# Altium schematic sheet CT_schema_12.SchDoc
size 632 x 434 mm
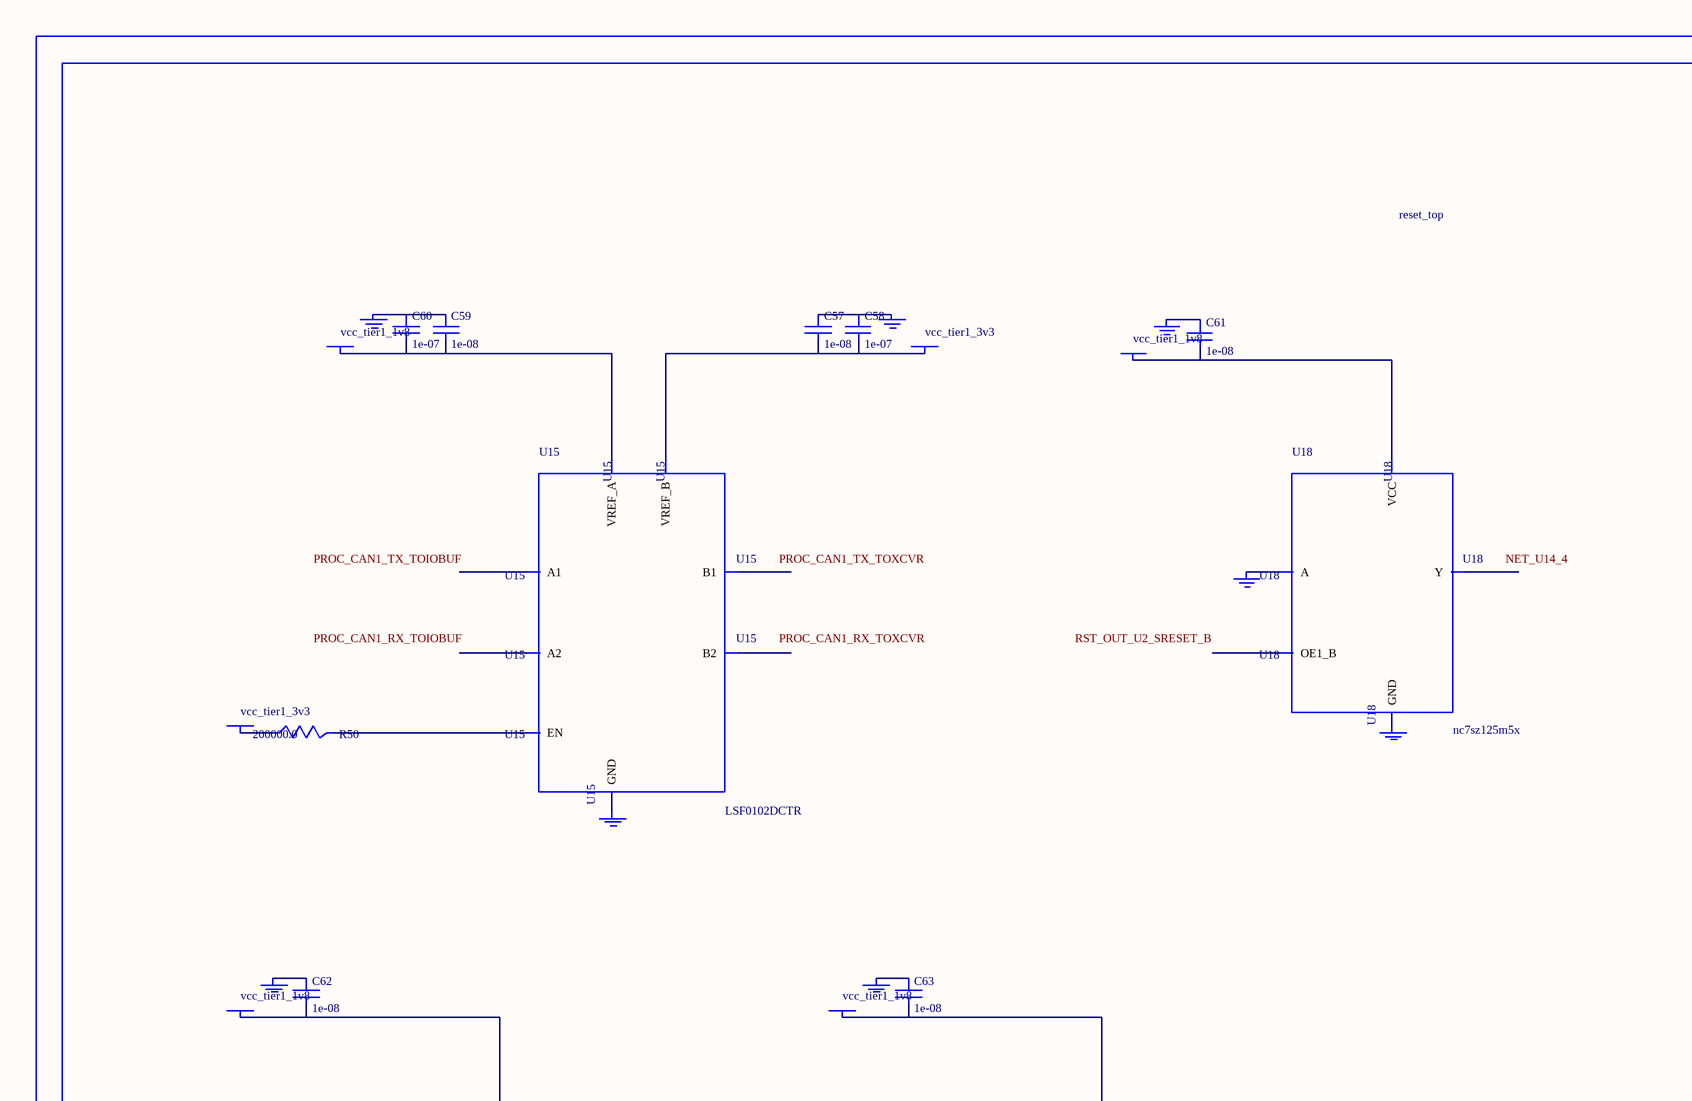
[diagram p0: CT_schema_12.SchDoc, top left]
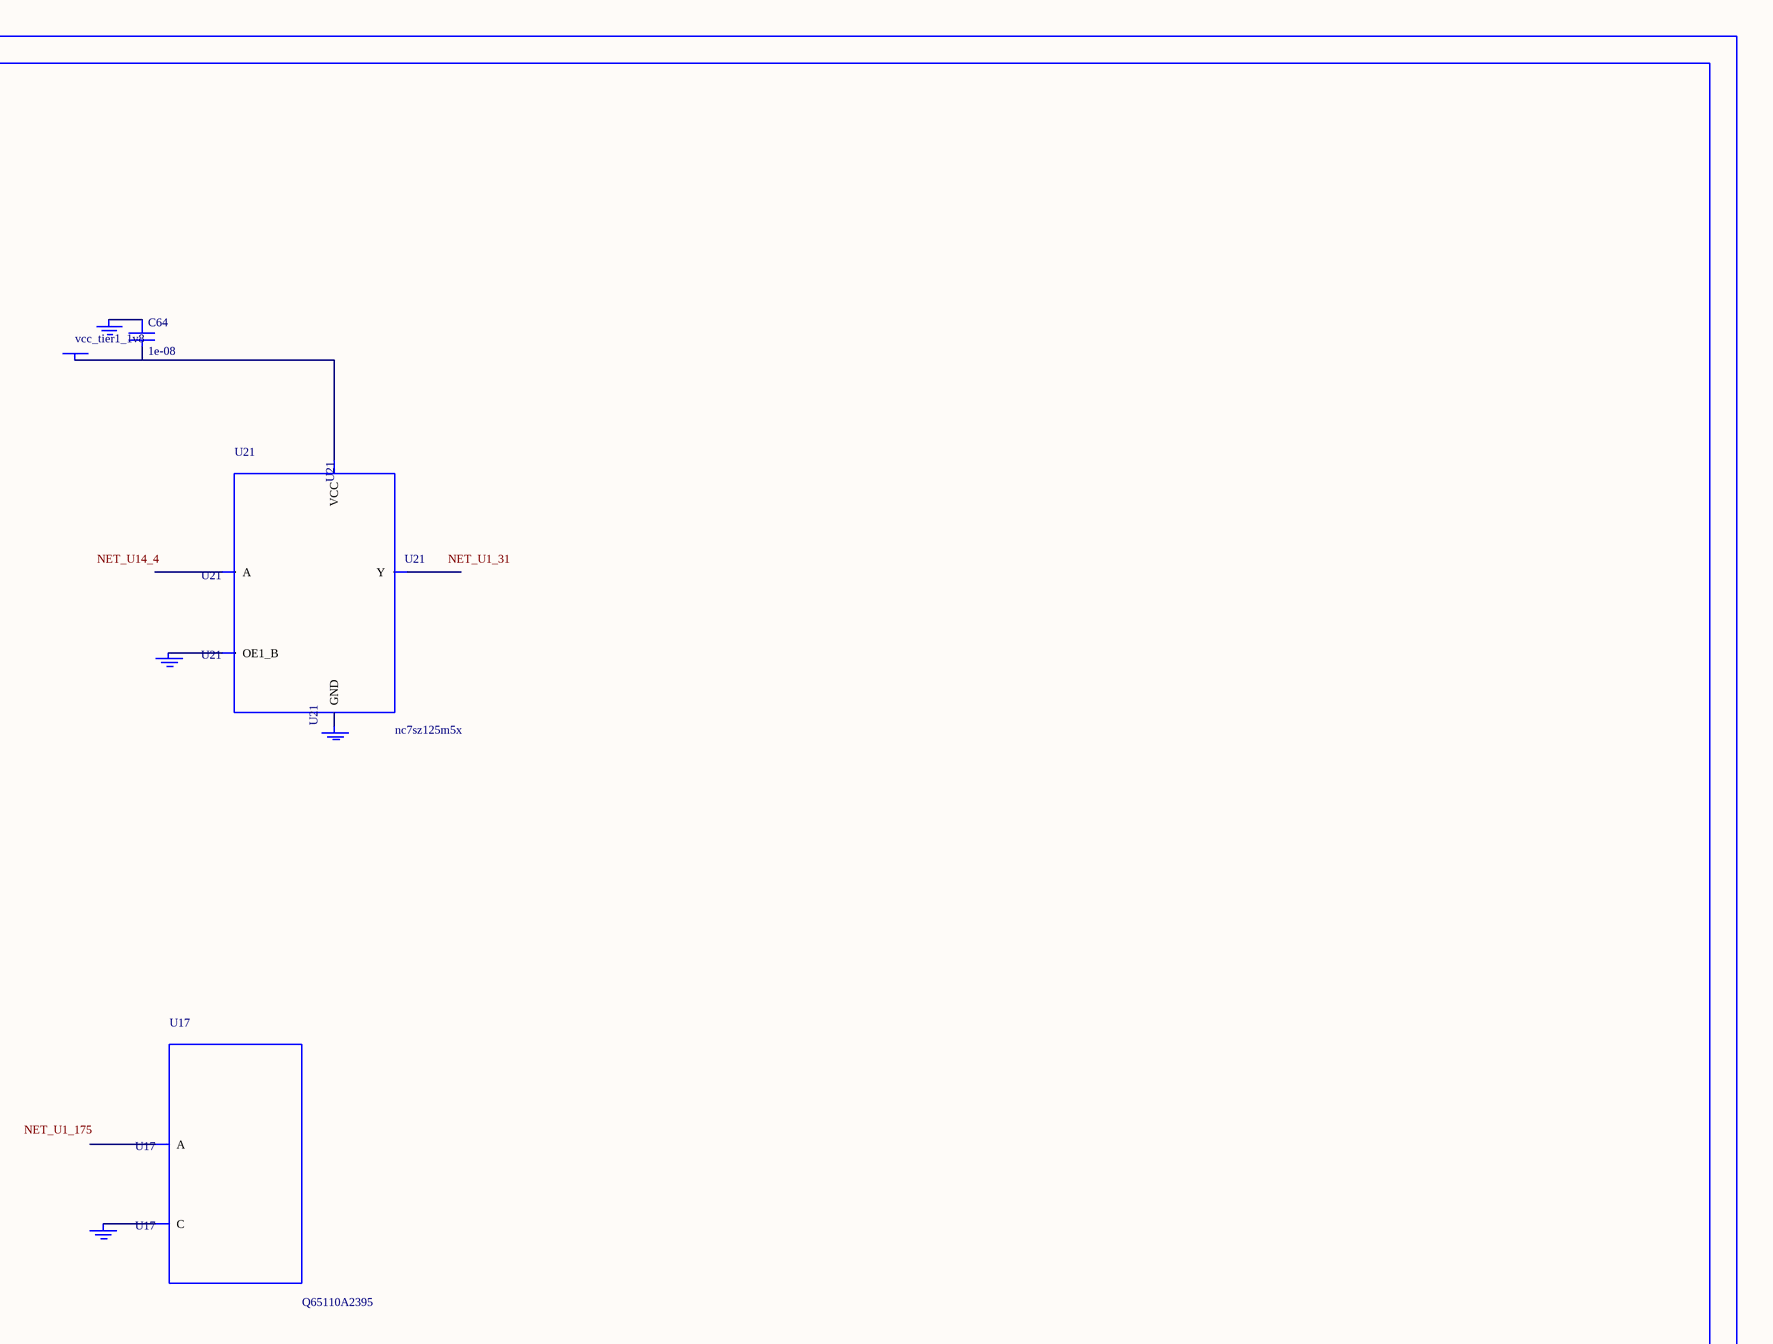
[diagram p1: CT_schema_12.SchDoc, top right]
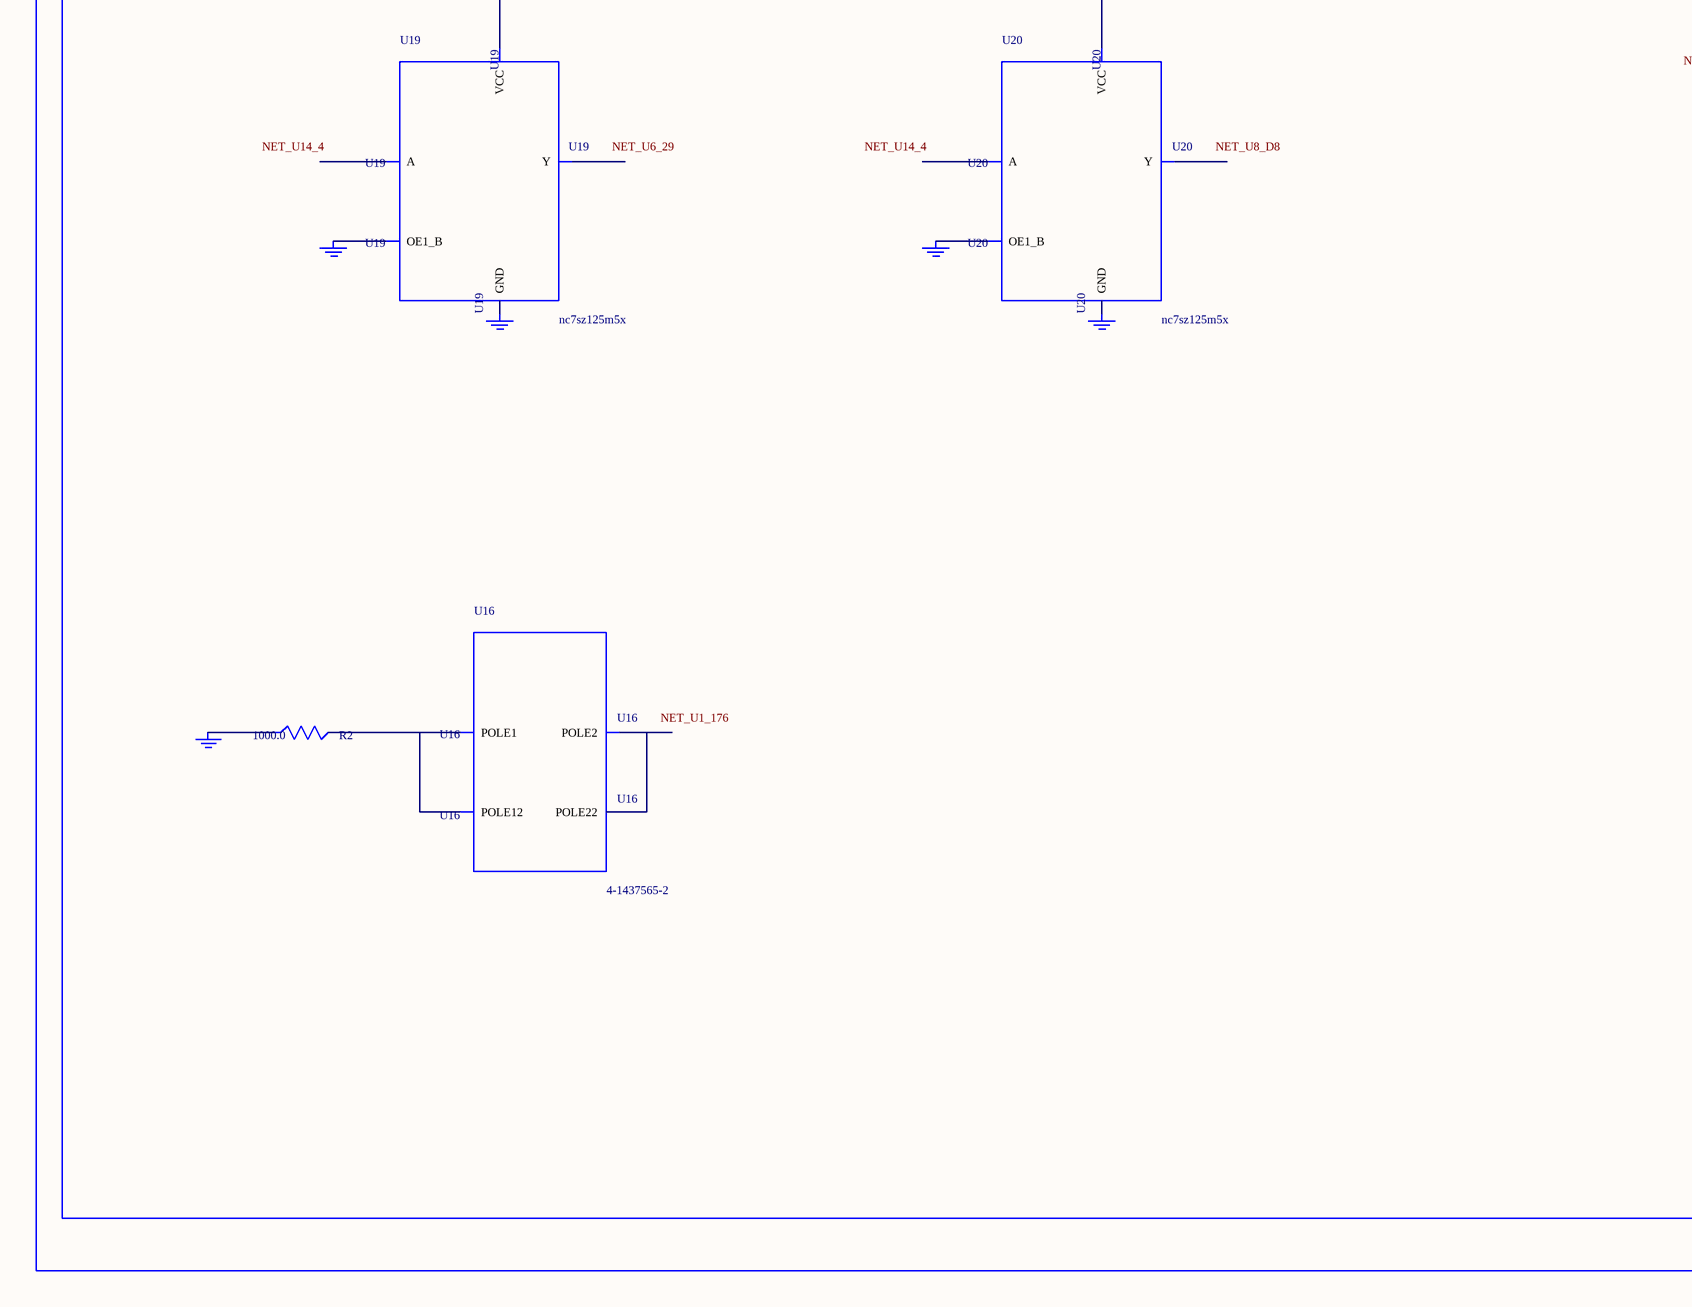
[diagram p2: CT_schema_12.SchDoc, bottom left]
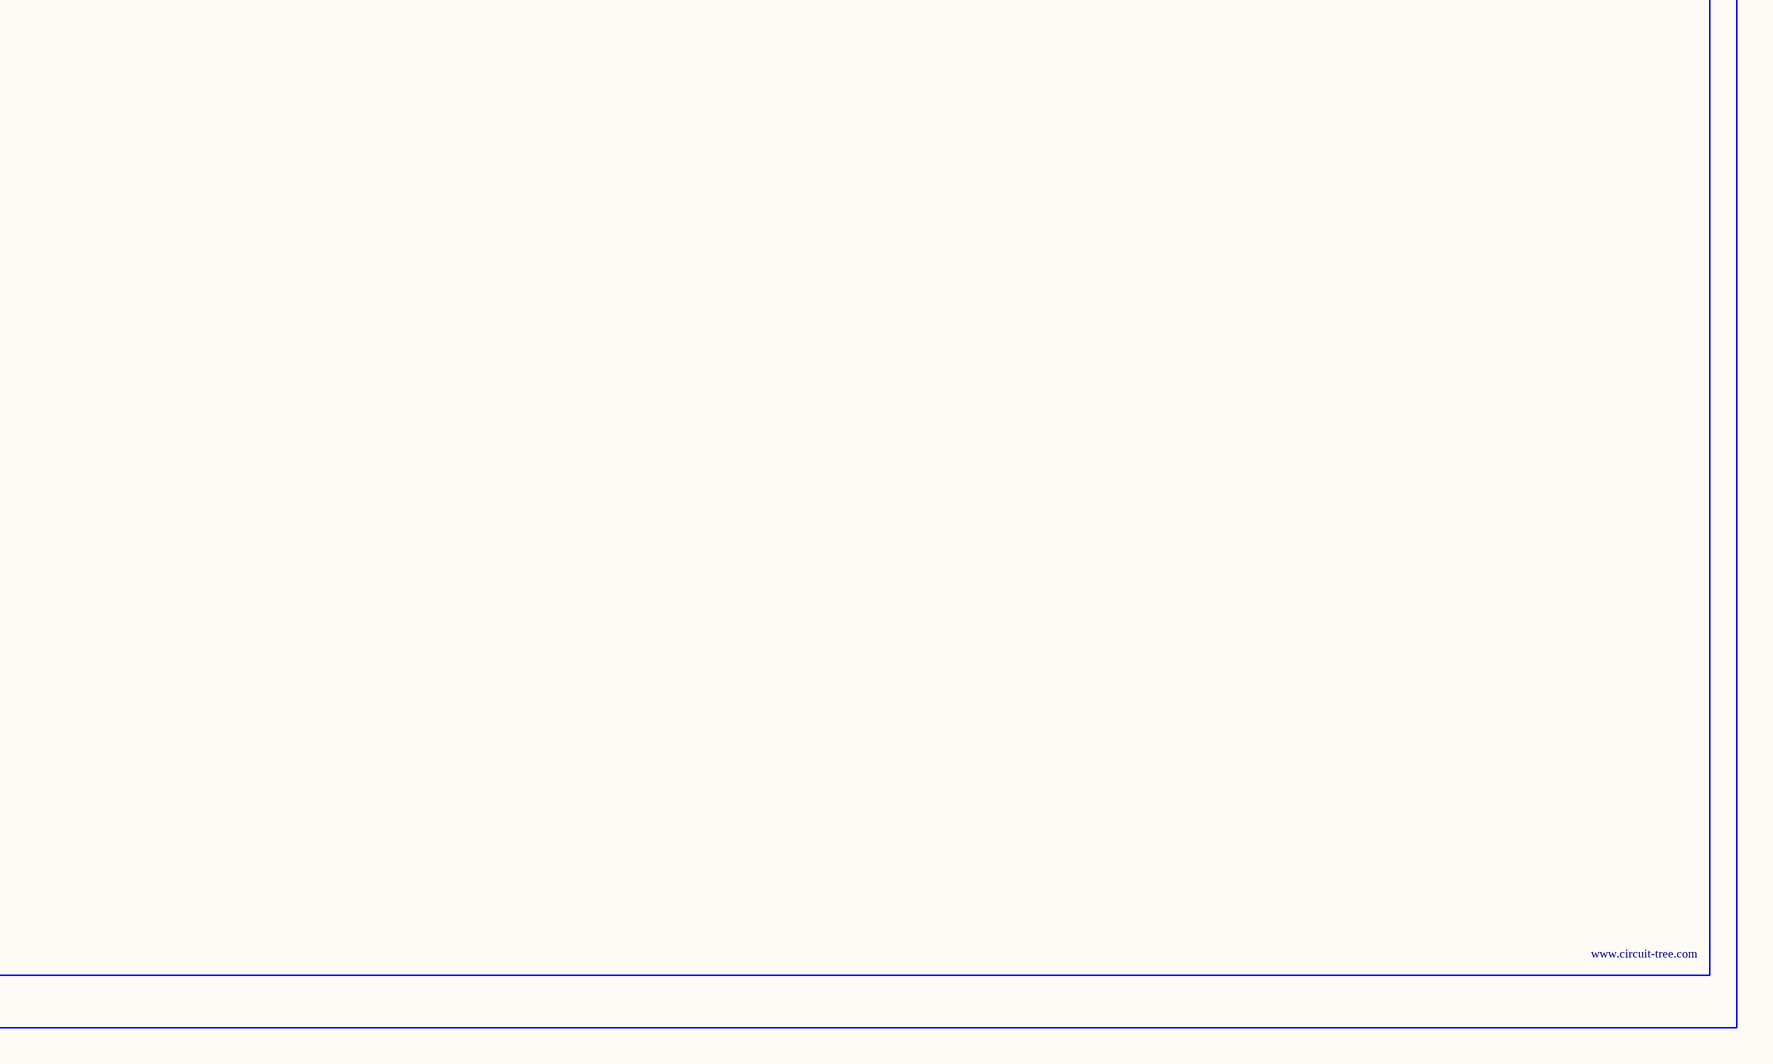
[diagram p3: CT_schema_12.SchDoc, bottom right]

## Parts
BORDER11  (no value)
C57  1e-08  [C0402]
C58  1e-07  [C0402]
C59  1e-08  [C0402]
C60  1e-07  [C0402]
C61  1e-08  [C0402]
C62  1e-08  [C0402]
C63  1e-08  [C0402]
C64  1e-08  [C0402]
GND_INSTANCE_11_0  (no value)
GND_INSTANCE_11_1  (no value)
GND_INSTANCE_11_2  (no value)
GND_INSTANCE_11_3  (no value)
GND_INSTANCE_11_4  (no value)
GND_INSTANCE_11_5  (no value)
GND_INSTANCE_11_6  (no value)
GND_INSTANCE_11_7  (no value)
GND_INSTANCE_11_8  (no value)
GND_INSTANCE_11_9  (no value)
GND_INSTANCE_11_10  (no value)
GND_INSTANCE_11_11  (no value)
GND_INSTANCE_11_12  (no value)
GND_INSTANCE_11_13  (no value)
GND_INSTANCE_11_14  (no value)
GND_INSTANCE_11_15  (no value)
GND_INSTANCE_11_16  (no value)
POWER_INSTANCE_11_0  vcc_tier1_1v8
POWER_INSTANCE_11_1  vcc_tier1_3v3
POWER_INSTANCE_11_2  vcc_tier1_3v3
POWER_INSTANCE_11_3  vcc_tier1_1v8
POWER_INSTANCE_11_4  vcc_tier1_1v8
POWER_INSTANCE_11_5  vcc_tier1_1v8
POWER_INSTANCE_11_6  vcc_tier1_1v8
R2  1000.0  [R0603]
R50  200000.0  [R0603]
U15  LSF0102DCTR  [DCU0008A_N]
U16  4-1437565-2  [SW_4-1437565-2]
U17  Q65110A2395  [LGM67K-G1J2-24-Z]
U18  nc7sz125m5x  [NC7SZ125M5X]
U19  nc7sz125m5x  [NC7SZ125M5X]
U20  nc7sz125m5x  [NC7SZ125M5X]
U21  nc7sz125m5x  [NC7SZ125M5X]

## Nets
NetC57_1: C57.1 C58.1 GND_INSTANCE_11_1.0(GND)
NetC57_2: C57.2 C58.2 POWER_INSTANCE_11_1.0(PWR) U15.7(VREF_B)
NetC59_1: C59.1 C60.1 GND_INSTANCE_11_0.0(GND)
NetC59_2: C59.2 C60.2 POWER_INSTANCE_11_0.0(PWR) U15.2(VREF_A)
NetC61_1: C61.1 GND_INSTANCE_11_5.0(GND)
NetC61_2: C61.2 POWER_INSTANCE_11_3.0(PWR) U18.5(VCC)
NetC62_1: C62.1 GND_INSTANCE_11_8.0(GND)
NetC62_2: C62.2 POWER_INSTANCE_11_4.0(PWR) U19.5(VCC)
NetC63_1: C63.1 GND_INSTANCE_11_11.0(GND)
NetC63_2: C63.2 POWER_INSTANCE_11_5.0(PWR) U20.5(VCC)
NetC64_1: C64.1 GND_INSTANCE_11_14.0(GND)
NetC64_2: C64.2 POWER_INSTANCE_11_6.0(PWR) U21.5(VCC)
NetGND_INSTANCE_11_2_0: GND_INSTANCE_11_2.0(GND) U15.1(GND)
NetGND_INSTANCE_11_3_0: GND_INSTANCE_11_3.0(GND) R2.1
NetGND_INSTANCE_11_4_0: GND_INSTANCE_11_4.0(GND) U17.C
NetGND_INSTANCE_11_6_0: GND_INSTANCE_11_6.0(GND) U18.2(A)
NetGND_INSTANCE_11_7_0: GND_INSTANCE_11_7.0(GND) U18.3(GND)
NetGND_INSTANCE_11_9_0: GND_INSTANCE_11_9.0(GND) U19.1(OE1_B)
NetGND_INSTANCE_11_10_0: GND_INSTANCE_11_10.0(GND) U19.3(GND)
NetGND_INSTANCE_11_12_0: GND_INSTANCE_11_12.0(GND) U20.1(OE1_B)
NetGND_INSTANCE_11_13_0: GND_INSTANCE_11_13.0(GND) U20.3(GND)
NetGND_INSTANCE_11_15_0: GND_INSTANCE_11_15.0(GND) U21.1(OE1_B)
NetGND_INSTANCE_11_16_0: GND_INSTANCE_11_16.0(GND) U21.3(GND)
NetPOWER_INSTANCE_11_2_0: POWER_INSTANCE_11_2.0(PWR) R50.1
NetR2_2: R2.2 U16.1(POLE1) U16.2(POLE12)
NetR50_2: R50.2 U15.8(EN)
NetU16_3: U16.3(POLE2) U16.4(POLE22)

Not connected (* = marked no-connect by the designer): U15 3(A1) 4(A2) 5(B2) 6(B1); U17 A; U18 1(OE1_B) 4(Y); U19 2(A) 4(Y); U20 2(A) 4(Y); U21 2(A) 4(Y)

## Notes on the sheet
- Labels drawn without touching a wire or pin: NET_U1_31, NET_U1_175, NET_U1_176, NET_U6_29, NET_U8_D8, NET_U14_4, PROC_CAN1_RX_TOIOBUF, PROC_CAN1_RX_TOXCVR, PROC_CAN1_TX_TOIOBUF, PROC_CAN1_TX_TOXCVR, RST_OUT_U2_SRESET_B

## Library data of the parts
BORDER11 = BORDER_PAGE11
C57 C59 C61-C64 = C0402C103K3RAC
C58 C60 = C0402C104K3RACTU
GND_INSTANCE_11_0-GND_INSTANCE_11_16 = GND
POWER_INSTANCE_11_0-POWER_INSTANCE_11_6 = PWR
R2 = RC0603JR-071KL
R50 = RC0603JR-07200KL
